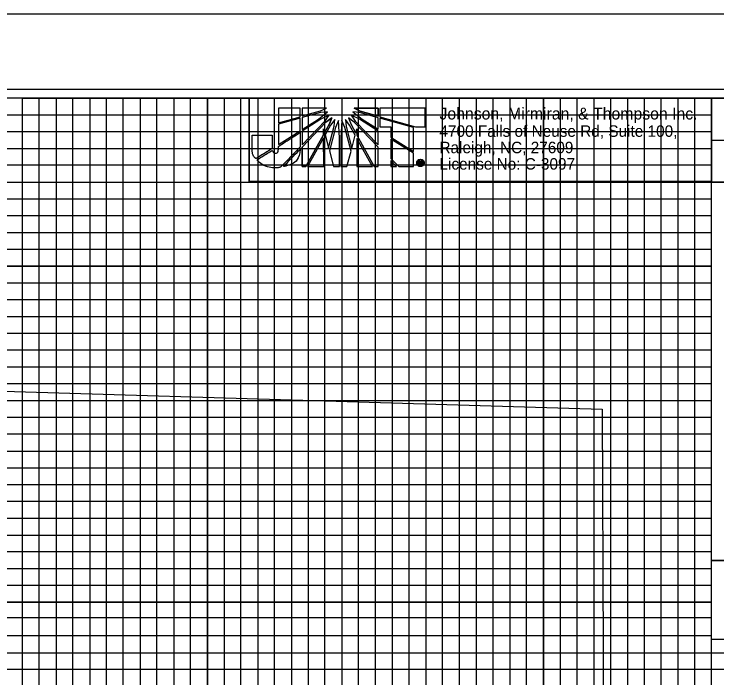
# Model space of a CAD drawing. Extents: x 1628636 to 1631253, y 896159 to 897520.
# Drawn here: x 1630319 to 1630528.1, y 897061.4 to 897258.9 of the extents above; entities that cross this region are included whole.
import ezdxf

# ---------------------------------------------------------------- set-up
doc = ezdxf.new("R2010")
doc.units = 0
for name, color, linetype in [('Default', 7, 'Continuous'), ('Prop PHM Black Shape', 7, 'Continuous'), ('Scratch_Level_6', 7, 'Continuous'), ('Sheet Cutting Line CELL', 7, 'Continuous'), ('Sheet DOT Grid CELL', 7, 'Continuous'), ('Sheet Plot Border Inside CELL', 7, 'Continuous'), ('Sheet Plot Border Outside CELL', 7, 'Continuous'), ('Sheet Profile CELL', 7, 'Continuous'), ('Sheet Profile Grid Major CELL', 7, 'Continuous'), ('Sheet Profile Grid Middle CELL', 7, 'Continuous'), ('Sheet Profile Grid Minor CELL', 7, 'Continuous'), ('Sheet Sticker Exception Certification CELL', 7, 'Continuous')]:
    doc.layers.add(name, color=color, linetype=linetype)

msp = doc.modelspace()

# ---------------------------------------------------------------- linework, layer by layer
at = {"layer": 'Default'}
for p, q in [((1630404.07, 897230.85), (1630397.63, 897230.85)), ((1630397.63, 897230.85), (1630397.63, 897226.58)), ((1630404.07, 897228.37), (1630404.07, 897230.85)), ((1630411.98, 897230.89), (1630404.73, 897230.89)), ((1630404.73, 897230.89), (1630404.74, 897228.58)), ((1630410.13, 897230.07), (1630411.98, 897230.89)), ((1630427.31, 897230.87), (1630420.18, 897230.9)), ((1630420.18, 897230.9), (1630421.98, 897230.05)), ((1630427.32, 897228.56), (1630427.31, 897230.87)), ((1630441.34, 897230.92), (1630427.81, 897230.91)), ((1630427.81, 897230.91), (1630427.81, 897228.42)), ((1630441.35, 897225.37), (1630441.34, 897230.92)), ((1630397.63, 897226.58), (1630404.07, 897228.37)), ((1630404.74, 897228.58), (1630410.13, 897230.07)), ((1630410.13, 897229.57), (1630404.74, 897228.08)), ((1630409.57, 897227.66), (1630412.23, 897229.83)), ((1630412.23, 897229.83), (1630410.13, 897229.57)), ((1630412.77, 897228.83), (1630410.31, 897227.59)), ((1630411.52, 897227.09), (1630412.77, 897228.83)), ((1630419.25, 897228.84), (1630420.5, 897227.07)), ((1630421.74, 897227.6), (1630419.25, 897228.84)), ((1630419.82, 897229.84), (1630422.52, 897227.63)), ((1630421.8, 897229.58), (1630419.82, 897229.84)), ((1630427.32, 897228.07), (1630421.8, 897229.58)), ((1630421.98, 897230.05), (1630427.32, 897228.56)), ((1630427.81, 897228.42), (1630427.81, 897228.35)), ((1630427.81, 897228.35), (1630438.47, 897225.37)), ((1630404.07, 897227.9), (1630397.63, 897226.09)), ((1630397.63, 897226.09), (1630397.64, 897220.09)), ((1630404.07, 897224.17), (1630404.07, 897227.9)), ((1630404.74, 897228.08), (1630404.74, 897224.6)), ((1630404.74, 897224.6), (1630409.57, 897227.66)), ((1630410.31, 897227.59), (1630404.74, 897224.04)), ((1630404.74, 897220.02), (1630411.52, 897227.09)), ((1630411.8, 897226.74), (1630404.74, 897219.34)), ((1630413.51, 897228.06), (1630411.8, 897226.74)), ((1630412.73, 897226), (1630413.51, 897228.06)), ((1630414.43, 897227.49), (1630413.16, 897225.85)), ((1630414.25, 897225.5), (1630414.43, 897227.49)), ((1630415.5, 897227.2), (1630414.62, 897225.14)), ((1630415.78, 897222.12), (1630415.5, 897227.2)), ((1630416.56, 897227.2), (1630416.23, 897222.12)), ((1630417.41, 897225.14), (1630416.56, 897227.2)), ((1630417.59, 897227.49), (1630417.8, 897225.43)), ((1630418.83, 897225.85), (1630417.59, 897227.49)), ((1630418.5, 897228.06), (1630419.29, 897226)), ((1630420.21, 897226.75), (1630418.5, 897228.06)), ((1630427.28, 897219.3), (1630420.21, 897226.75)), ((1630420.5, 897227.07), (1630427.28, 897219.97)), ((1630427.28, 897224.09), (1630421.74, 897227.6)), ((1630422.52, 897227.63), (1630427.28, 897224.66)), ((1630427.28, 897224.66), (1630427.32, 897228.07)), ((1630427.81, 897227.97), (1630427.81, 897227.92)), ((1630437.79, 897225.13), (1630427.81, 897227.97)), ((1630427.81, 897227.92), (1630427.82, 897225.33)), ((1630397.64, 897220.09), (1630404.07, 897224.17)), ((1630404.74, 897224.04), (1630404.74, 897220.02)), ((1630411.06, 897223.01), (1630411.06, 897224.71)), ((1630411.06, 897224.71), (1630411.38, 897223.54)), ((1630411.38, 897223.54), (1630412.73, 897226)), ((1630413.16, 897225.85), (1630411.56, 897222.94)), ((1630412.59, 897219.07), (1630414.25, 897225.5)), ((1630414.62, 897225.14), (1630412.81, 897218.18)), ((1630419.26, 897218.08), (1630417.41, 897225.14)), ((1630417.8, 897225.43), (1630419.47, 897218.93)), ((1630420.5, 897222.84), (1630418.83, 897225.85)), ((1630419.29, 897226), (1630420.67, 897223.45)), ((1630420.67, 897223.45), (1630421, 897224.72)), ((1630421, 897224.72), (1630421, 897222.84)), ((1630427.28, 897219.97), (1630427.28, 897224.09)), ((1630427.82, 897225.33), (1630431.12, 897225.33)), ((1630431.12, 897225.33), (1630431.12, 897222.24)), ((1630437.8, 897218.02), (1630437.79, 897225.13)), ((1630438.47, 897225.37), (1630441.35, 897225.37)), ((1630405.81, 897213.5), (1630411.06, 897223.01)), ((1630411.06, 897222.09), (1630406.31, 897213.5)), ((1630411.11, 897213.51), (1630411.06, 897222.09)), ((1630411.56, 897222.94), (1630412.59, 897219.07)), ((1630415.78, 897213.54), (1630415.78, 897222.12)), ((1630416.23, 897222.12), (1630416.24, 897213.54)), ((1630419.47, 897218.93), (1630420.5, 897222.84)), ((1630421, 897222.84), (1630426.15, 897213.52)), ((1630425.62, 897213.55), (1630421, 897221.92)), ((1630421, 897221.92), (1630421.01, 897213.55)), ((1630431.12, 897222.24), (1630437.8, 897218.02)), ((1630431.12, 897221.71), (1630431.13, 897215.96)), ((1630437.8, 897217.52), (1630431.12, 897221.71)), ((1630404.74, 897219.34), (1630404.75, 897213.5)), ((1630412.81, 897218.18), (1630414.02, 897213.54)), ((1630418.02, 897213.55), (1630419.26, 897218.08)), ((1630427.29, 897213.52), (1630427.28, 897219.3)), ((1630431.13, 897215.96), (1630433.43, 897213.53)), ((1630437.8, 897213.53), (1630437.8, 897217.52)), ((1630439.89, 897215.7), (1630439.89, 897215.5)), ((1630439.89, 897215.5), (1630439.89, 897215.7)), ((1630414.02, 897213.54), (1630415.78, 897213.54)), ((1630416.24, 897213.54), (1630418.02, 897213.55)), ((1630421.01, 897213.55), (1630425.62, 897213.55)), ((1630426.15, 897213.52), (1630427.29, 897213.52)), ((1630432.8, 897213.53), (1630431.13, 897215.33)), ((1630431.13, 897215.33), (1630431.13, 897213.52)), ((1630431.13, 897213.52), (1630432.8, 897213.53)), ((1630433.43, 897213.53), (1630437.8, 897213.53)), ((1630439.49, 897214.14), (1630439.49, 897215.12)), ((1630439.49, 897215.12), (1630439.9, 897215.12)), ((1630439.72, 897214.14), (1630439.49, 897214.14)), ((1630439.9, 897214.94), (1630439.72, 897214.94)), ((1630439.72, 897214.94), (1630439.72, 897214.7)), ((1630439.72, 897214.7), (1630439.9, 897214.7)), ((1630439.9, 897214.52), (1630439.72, 897214.52)), ((1630439.72, 897214.52), (1630439.72, 897214.14)), ((1630439.9, 897215.12), (1630439.9, 897214.94)), ((1630439.9, 897214.94), (1630439.9, 897215.12)), ((1630439.9, 897215.12), (1630439.96, 897215.12)), ((1630439.92, 897214.94), (1630439.9, 897214.94)), ((1630439.9, 897214.7), (1630439.9, 897214.52)), ((1630439.9, 897214.52), (1630439.9, 897214.7)), ((1630439.9, 897214.7), (1630439.9, 897214.7)), ((1630439.9, 897214.52), (1630439.9, 897214.52)), ((1630439.9, 897213.76), (1630439.9, 897213.54)), ((1630439.9, 897213.54), (1630439.9, 897213.76)), ((1630439.9, 897213.76), (1630439.91, 897213.76)), ((1630439.91, 897213.54), (1630439.9, 897213.54)), ((1630404.75, 897213.5), (1630405.81, 897213.5)), ((1630406.31, 897213.5), (1630411.11, 897213.51))]:
    msp.add_line(p, q, dxfattribs=at)
for points in [[(1630388.92, 897209.08), (1630526.45, 897209.06), (1630526.45, 897233.88), (1630388.93, 897233.9)], [(1630420.18, 897230.9), (1630427.31, 897230.87), (1630427.32, 897228.56), (1630421.98, 897230.05)], [(1630404.75, 897213.5), (1630404.74, 897219.34), (1630411.8, 897226.74), (1630413.51, 897228.06), (1630412.94, 897226.43), (1630411.38, 897223.54), (1630411.06, 897224.71), (1630411.06, 897223.01), (1630405.81, 897213.5)]]:
    msp.add_lwpolyline(points, close=True, dxfattribs=at)
for points in [[(1630397.63, 897226.58), (1630404.07, 897228.37), (1630404.07, 897230.85), (1630397.63, 897230.85), (1630397.63, 897226.58)], [(1630410.13, 897230.07), (1630411.98, 897230.89), (1630404.73, 897230.89), (1630404.74, 897228.58), (1630410.13, 897230.07)], [(1630421.98, 897230.05), (1630427.32, 897228.56), (1630427.31, 897230.87), (1630420.18, 897230.9), (1630421.98, 897230.05)], [(1630441.34, 897230.92), (1630427.81, 897230.91), (1630427.81, 897228.42), (1630427.81, 897228.35), (1630438.47, 897225.37), (1630441.35, 897225.37), (1630441.34, 897230.92)], [(1630404.74, 897228.08), (1630404.74, 897224.6), (1630409.57, 897227.66), (1630412.23, 897229.83), (1630410.13, 897229.57), (1630404.74, 897228.08)], [(1630404.74, 897224.04), (1630404.74, 897220.02), (1630411.52, 897227.09), (1630412.77, 897228.83), (1630410.31, 897227.59), (1630404.74, 897224.04)], [(1630419.25, 897228.84), (1630420.5, 897227.07), (1630427.28, 897219.97), (1630427.28, 897224.09), (1630421.74, 897227.6), (1630419.25, 897228.84)], [(1630419.82, 897229.84), (1630422.52, 897227.63), (1630427.28, 897224.66), (1630427.32, 897228.07), (1630421.8, 897229.58), (1630419.82, 897229.84)], [(1630397.64, 897220.09), (1630404.07, 897224.17), (1630404.07, 897227.9), (1630397.63, 897226.09), (1630397.64, 897220.09)], [(1630413.51, 897228.06), (1630411.8, 897226.74), (1630404.74, 897219.34), (1630404.75, 897213.5), (1630405.81, 897213.5), (1630411.06, 897223.01), (1630411.06, 897224.71), (1630411.38, 897223.54), (1630412.73, 897226), (1630413.51, 897228.06)], [(1630414.43, 897227.49), (1630413.16, 897225.85), (1630411.56, 897222.94), (1630412.59, 897219.07), (1630414.25, 897225.5), (1630414.43, 897227.49)], [(1630414.62, 897225.14), (1630412.81, 897218.18), (1630414.02, 897213.54), (1630415.78, 897213.54), (1630415.78, 897222.12), (1630415.5, 897227.2), (1630414.62, 897225.14)], [(1630416.56, 897227.2), (1630416.23, 897222.12), (1630416.24, 897213.54), (1630418.02, 897213.55), (1630419.26, 897218.08), (1630417.41, 897225.14), (1630416.56, 897227.2)], [(1630417.59, 897227.49), (1630417.8, 897225.43), (1630419.47, 897218.93), (1630420.5, 897222.84), (1630418.83, 897225.85), (1630417.59, 897227.49)], [(1630418.5, 897228.06), (1630419.29, 897226), (1630420.67, 897223.45), (1630421, 897224.72), (1630421, 897222.84), (1630426.15, 897213.52), (1630427.29, 897213.52), (1630427.28, 897219.3), (1630420.21, 897226.75), (1630418.5, 897228.06)], [(1630427.81, 897227.97), (1630427.81, 897227.92), (1630427.82, 897225.33), (1630431.12, 897225.33), (1630431.12, 897222.24), (1630437.8, 897218.02), (1630437.79, 897225.13), (1630427.81, 897227.97)], [(1630406.31, 897213.5), (1630411.11, 897213.51), (1630411.06, 897222.09), (1630406.31, 897213.5)], [(1630421.01, 897213.55), (1630425.62, 897213.55), (1630421, 897221.92), (1630421.01, 897213.55)], [(1630431.12, 897221.71), (1630431.13, 897215.96), (1630433.43, 897213.53), (1630437.8, 897213.53), (1630437.8, 897217.52), (1630431.12, 897221.71), (1630431.12, 897221.71)], [(1630431.13, 897213.52), (1630431.13, 897213.52), (1630432.8, 897213.53), (1630431.13, 897215.33), (1630431.13, 897213.52)], [(1630440.33, 897214.37), (1630440.33, 897214.32), (1630440.33, 897214.28), (1630440.33, 897214.25), (1630440.36, 897214.14), (1630440.16, 897214.14)]]:
    msp.add_lwpolyline(points, dxfattribs=at)
for points, degree in [([(1630395.79, 897222.85), (1630395.79, 897222.85), (1630389.83, 897222.85), (1630389.83, 897222.85), (1630389.83, 897222.85), (1630389.83, 897219.12), (1630389.83, 897219.12), (1630389.83, 897219.12), (1630389.83, 897218.72), (1630389.83, 897218.72), (1630389.84, 897217.56), (1630390.22, 897216.63), (1630390.9, 897215.86), (1630390.9, 897215.86), (1630395.79, 897218.84), (1630395.79, 897218.91), (1630395.79, 897218.91), (1630395.79, 897222.85), (1630395.79, 897222.85)], 3), ([(1630396.72, 897217.49), (1630396.33, 897217.49), (1630396.01, 897217.7), (1630395.87, 897218.41), (1630395.87, 897218.41), (1630391.25, 897215.55), (1630391.25, 897215.55), (1630392.67, 897214.05), (1630394.95, 897213.16), (1630396.87, 897213.17), (1630397.37, 897213.17), (1630397.75, 897213.21), (1630398.28, 897213.32), (1630398.28, 897213.32), (1630404.08, 897219.31), (1630404.08, 897219.31), (1630404.08, 897219.31), (1630404.07, 897223.64), (1630404.07, 897223.64), (1630404.07, 897223.64), (1630397.64, 897219.55), (1630397.64, 897219.55), (1630397.64, 897217.92), (1630397.25, 897217.49), (1630396.72, 897217.49)], 3), ([(1630396.72, 897217.49), (1630396.33, 897217.49), (1630396.01, 897217.7), (1630395.87, 897218.41), (1630395.87, 897218.41), (1630391.25, 897215.55), (1630391.25, 897215.55), (1630392.67, 897214.05), (1630394.95, 897213.16), (1630396.87, 897213.17), (1630397.37, 897213.17), (1630397.75, 897213.21), (1630398.28, 897213.32), (1630398.28, 897213.32), (1630404.08, 897219.31), (1630404.08, 897219.31), (1630404.08, 897219.31), (1630404.07, 897223.64), (1630404.07, 897223.64), (1630404.07, 897223.64), (1630397.64, 897219.55), (1630397.64, 897219.55), (1630397.64, 897217.92), (1630397.25, 897217.49), (1630396.72, 897217.49)], 3), ([(1630404.08, 897218.63), (1630404.08, 897218.63), (1630399.07, 897213.45), (1630399.07, 897213.45), (1630401.52, 897214.06), (1630403.96, 897215.69), (1630404.08, 897218.63)], 3), ([(1630439.9, 897213.54), (1630439.6, 897213.54), (1630439.34, 897213.65), (1630439.13, 897213.86), (1630438.91, 897214.07), (1630438.8, 897214.33), (1630438.8, 897214.63), (1630438.8, 897214.93), (1630438.91, 897215.19), (1630439.13, 897215.39), (1630439.34, 897215.6), (1630439.59, 897215.7), (1630439.89, 897215.7)], 3), ([(1630439.89, 897215.7), (1630440.2, 897215.71), (1630440.46, 897215.6), (1630440.67, 897215.39), (1630440.89, 897215.2), (1630441, 897214.94), (1630441, 897214.63)], 3), ([(1630439.89, 897215.5), (1630439.65, 897215.5), (1630439.45, 897215.42), (1630439.28, 897215.26), (1630439.11, 897215.09), (1630439.02, 897214.87), (1630439.02, 897214.63), (1630439.02, 897214.39), (1630439.11, 897214.17), (1630439.28, 897214), (1630439.45, 897213.84), (1630439.65, 897213.75), (1630439.9, 897213.76)], 3), ([(1630439.91, 897213.76), (1630440.15, 897213.76), (1630440.35, 897213.84), (1630440.52, 897214.01), (1630440.69, 897214.18), (1630440.78, 897214.39), (1630440.78, 897214.63), (1630440.78, 897214.87), (1630440.69, 897215.09), (1630440.52, 897215.26), (1630440.35, 897215.42), (1630440.15, 897215.5), (1630439.89, 897215.5)], 3), ([(1630439.9, 897214.7), (1630440.05, 897214.7), (1630440.12, 897214.75), (1630440.12, 897214.83), (1630440.12, 897214.9), (1630440.06, 897214.94), (1630439.92, 897214.94)], 3), ([(1630440.07, 897214.49), (1630440.05, 897214.51), (1630439.99, 897214.52), (1630439.9, 897214.52)], 2), ([(1630441, 897214.63), (1630441, 897214.33), (1630440.89, 897214.07), (1630440.68, 897213.85), (1630440.47, 897213.65), (1630440.21, 897213.54), (1630439.91, 897213.54)], 3), ([(1630439.96, 897215.12), (1630440.21, 897215.12), (1630440.33, 897215.03), (1630440.33, 897214.83), (1630440.33, 897214.74), (1630440.3, 897214.67), (1630440.22, 897214.61)], 3), ([(1630440.16, 897214.14), (1630440.13, 897214.19), (1630440.11, 897214.25), (1630440.11, 897214.32), (1630440.11, 897214.41), (1630440.1, 897214.46), (1630440.07, 897214.49)], 3), ([(1630440.22, 897214.61), (1630440.28, 897214.58), (1630440.32, 897214.5), (1630440.33, 897214.37)], 2)]:
    msp.add_open_spline(points, degree=degree, dxfattribs=at)
at = {"layer": 'Prop PHM Black Shape'}
msp.add_lwpolyline([(1630388.92, 897233.9), (1630526.45, 897233.9), (1630526.45, 897209.06), (1630388.92, 897209.06)], close=True, dxfattribs=at)
at = {"layer": 'Scratch_Level_6'}
for points in [[(1629976.5, 897183.9), (1630476.5, 897183.9), (1630476.5, 896758.9), (1629976.5, 896758.9)], [(1630074.97, 896969.15), (1630075.03, 897039.83), (1630065.35, 897048.31), (1630064.94, 897154.26), (1630493.96, 897141.36), (1630495.42, 896780.43), (1630074.26, 896783.19)]]:
    msp.add_lwpolyline(points, close=True, dxfattribs=at)
at = {"layer": 'Sheet Cutting Line CELL'}
msp.add_line((1630743.5, 897258.9), (1629059.5, 897258.9), dxfattribs=at)
at = {"layer": 'Sheet DOT Grid CELL'}
for p, q in [((1630326.5, 896733.9), (1630326.5, 897233.9)), ((1630376.5, 896733.9), (1630376.5, 897233.9)), ((1630426.5, 896733.9), (1630426.5, 897233.9)), ((1630476.5, 896733.9), (1630476.5, 897233.9)), ((1630526.45, 897183.9), (1629226.5, 897183.9)), ((1630526.45, 897133.9), (1629226.5, 897133.9)), ((1630526.5, 896733.9), (1630526.5, 897096.35)), ((1630526.5, 897083.9), (1629226.5, 897083.9))]:
    msp.add_line(p, q, dxfattribs=at)
at = {"layer": 'Sheet Plot Border Inside CELL'}
msp.add_lwpolyline([(1629072.5, 896181.35), (1630739, 896181.35), (1630739, 897236.45), (1629072.5, 897236.45)], close=True, dxfattribs=at)
at = {"layer": 'Sheet Plot Border Outside CELL'}
msp.add_lwpolyline([(1629059.5, 896158.9), (1630743.5, 896158.9), (1630743.5, 897258.9), (1629059.5, 897258.9)], close=True, dxfattribs=at)
at = {"layer": 'Sheet Profile CELL'}
msp.add_line((1630526.45, 897221.35), (1630726.5, 897221.35), dxfattribs=at)
for points in [[(1630726.5, 897233.9), (1629226.5, 897233.9), (1629226.5, 896183.9), (1630726.5, 896183.9)], [(1630526.45, 897233.9), (1630726.5, 897233.9), (1630726.5, 897208.85), (1630526.45, 897208.85)], [(1630526.45, 897208.85), (1630626.5, 897208.85), (1630626.5, 897096.35), (1630526.45, 897096.35)]]:
    msp.add_lwpolyline(points, close=True, dxfattribs=at)
at = {"layer": 'Sheet Profile Grid Major CELL'}
for points in [[(1630126.5, 897095.37), (1630126.5, 897233.9), (1630176.5, 897233.9), (1630176.5, 896733.9), (1630226.5, 896733.9), (1630226.5, 897233.9), (1630276.5, 897233.9), (1630276.5, 896733.9), (1630326.5, 896733.9), (1630326.5, 897233.9), (1630376.5, 897233.9), (1630376.5, 896733.9), (1630426.5, 896733.9), (1630426.5, 897233.9), (1630476.5, 897233.9), (1630476.5, 896733.9), (1630526.5, 896733.9), (1630526.5, 897233.9), (1630552.8, 897233.9)], [(1629226.5, 897183.9), (1630526.5, 897183.9)], [(1630526.5, 897133.9), (1629226.5, 897133.9), (1629226.5, 897083.9), (1630526.5, 897083.9)]]:
    msp.add_lwpolyline(points, dxfattribs=at)
at = {"layer": 'Sheet Profile Grid Middle CELL'}
msp.add_line((1629226.5, 897208.9), (1630526.45, 897208.9), dxfattribs=at)
for points in [[(1630151.5, 897093.9), (1630151.5, 897233.9), (1630201.5, 897233.9), (1630201.5, 896733.9), (1630251.5, 896733.9), (1630251.5, 897233.9), (1630301.5, 897233.9), (1630301.5, 896733.9), (1630351.5, 896733.9), (1630351.5, 897233.9), (1630401.5, 897233.9), (1630401.5, 896733.9), (1630451.5, 896733.9), (1630451.5, 897233.9), (1630501.5, 897233.9), (1630501.5, 896733.9), (1630551.5, 896733.9), (1630551.5, 897072.85)], [(1630526.5, 897158.9), (1629226.5, 897158.9), (1629226.5, 897108.9), (1630526.5, 897108.9)]]:
    msp.add_lwpolyline(points, dxfattribs=at)
at = {"layer": 'Sheet Profile Grid Minor CELL'}
for p, q in [((1630321.5, 896733.9), (1630321.5, 897233.9)), ((1630321.5, 897233.9), (1630331.5, 897233.9)), ((1630331.5, 897233.9), (1630331.5, 896733.9)), ((1630336.5, 896733.9), (1630336.5, 897233.9)), ((1630336.5, 897233.9), (1630341.5, 897233.9)), ((1630341.5, 897233.9), (1630341.5, 896733.9)), ((1630346.5, 896733.9), (1630346.5, 897233.9)), ((1630346.5, 897233.9), (1630356.5, 897233.9)), ((1630356.5, 897233.9), (1630356.5, 896733.9)), ((1630361.5, 896733.9), (1630361.5, 897233.9)), ((1630361.5, 897233.9), (1630366.5, 897233.9)), ((1630366.5, 897233.9), (1630366.5, 896733.9)), ((1630371.5, 896733.9), (1630371.5, 897233.9)), ((1630371.5, 897233.9), (1630381.5, 897233.9)), ((1630381.5, 897233.9), (1630381.5, 896733.9)), ((1630386.5, 896733.9), (1630386.5, 897233.9)), ((1630386.5, 897233.9), (1630391.5, 897233.9)), ((1630391.5, 897233.9), (1630391.5, 896733.9)), ((1630396.5, 896733.9), (1630396.5, 897233.9)), ((1630396.5, 897233.9), (1630406.5, 897233.9)), ((1630406.5, 897233.9), (1630406.5, 896733.9)), ((1630411.5, 896733.9), (1630411.5, 897233.9)), ((1630411.5, 897233.9), (1630416.5, 897233.9)), ((1630416.5, 897233.9), (1630416.5, 896733.9)), ((1629276.5, 897228.9), (1630526.5, 897228.9)), ((1630526.5, 897223.9), (1629276.5, 897223.55)), ((1629276.5, 897218.9), (1630526.5, 897218.9)), ((1630526.45, 897098.9), (1629276.5, 897098.9)), ((1630526.5, 897093.9), (1629276.5, 897093.9)), ((1630526.5, 897088.9), (1630171.34, 897088.9)), ((1630526.5, 897079.25), (1630171.5, 897079.25)), ((1630526.5, 897073.9), (1630171.5, 897073.9)), ((1630171.5, 897068.9), (1630676.5, 897068.9))]:
    msp.add_line(p, q, dxfattribs=at)
for points in [[(1630421.5, 896733.9), (1630421.5, 897233.9), (1630431.5, 897233.9), (1630431.5, 896733.9)], [(1630436.5, 896733.9), (1630436.5, 897233.9), (1630441.5, 897233.9), (1630441.5, 896733.9)], [(1630446.5, 896733.9), (1630446.5, 897233.9), (1630456.5, 897233.9), (1630456.5, 896733.9)], [(1630461.5, 896733.9), (1630461.5, 897233.9), (1630466.5, 897233.9), (1630466.5, 896733.9)], [(1630471.5, 896733.9), (1630471.5, 897233.9), (1630481.5, 897233.9), (1630481.5, 896733.9)], [(1630486.5, 896733.9), (1630486.5, 897233.9), (1630491.5, 897233.9), (1630491.5, 896733.9)], [(1630496.5, 896733.9), (1630496.5, 897233.9), (1630506.5, 897233.9), (1630506.5, 896733.9)], [(1630511.5, 896733.9), (1630511.5, 897233.9), (1630516.5, 897233.9), (1630516.5, 896733.9)], [(1630521.5, 896733.9), (1630521.5, 897233.9), (1630531.5, 897233.9)], [(1630526.5, 897213.9), (1629276.5, 897213.9), (1629276.5, 897203.9), (1630526.5, 897203.9)], [(1630526.45, 897198.9), (1629276.5, 897198.9), (1629276.5, 897193.9), (1630526.5, 897193.9)], [(1630526.5, 897188.9), (1629276.5, 897188.9), (1629276.5, 897178.9), (1630526.5, 897178.9)], [(1630526.5, 897173.9), (1629276.5, 897173.9), (1629276.5, 897168.9), (1630526.5, 897168.9)], [(1630526.5, 897163.9), (1629276.5, 897163.9), (1629276.5, 897153.9), (1630526.5, 897153.9)], [(1630526.5, 897148.9), (1629276.5, 897148.9), (1629276.5, 897143.9), (1630526.5, 897143.9)], [(1630526.5, 897138.9), (1629276.5, 897138.9), (1629276.5, 897128.9), (1630526.5, 897128.9)], [(1630526.5, 897123.8), (1629276.6, 897123.8), (1629276.6, 897118.9), (1630526.5, 897118.9)], [(1630526.5, 897113.9), (1629276.5, 897113.9), (1629276.5, 897103.9), (1630526.5, 897103.9)], [(1630676.5, 897063.9), (1630171.5, 897063.9)]]:
    msp.add_lwpolyline(points, dxfattribs=at)
at = {"layer": 'Sheet Sticker Exception Certification CELL'}
for p, q in [((1630526.45, 897072.85), (1630526.45, 897096.35)), ((1630526.45, 897096.35), (1630726.49, 897096.35)), ((1630526.45, 897072.85), (1630526.45, 897096.35)), ((1630526.45, 897096.35), (1630726.49, 897096.35)), ((1630726.49, 897072.85), (1630526.45, 897072.85)), ((1630726.49, 897072.85), (1630526.45, 897072.85))]:
    msp.add_line(p, q, dxfattribs=at)

# ---------------------------------------------------------------- texts
at = {"layer": 'Default'}
for s, height, p in [('Johnson, Mirmiran, & Thompson Inc.', 3.5139, (1630445.56, 897227.53)), ('4700 Falls of Neuse Rd, Suite 100, ', 3.4135, (1630445.56, 897222.38)), ('Raleigh, NC, 27609', 3.4135, (1630445.56, 897217.5)), ('License No: C-3097', 3.4135, (1630445.56, 897212.62))]:
    msp.add_text(s, height=height, rotation=359.9946, dxfattribs=at).set_placement(p)

doc.saveas('drawing.dxf')
